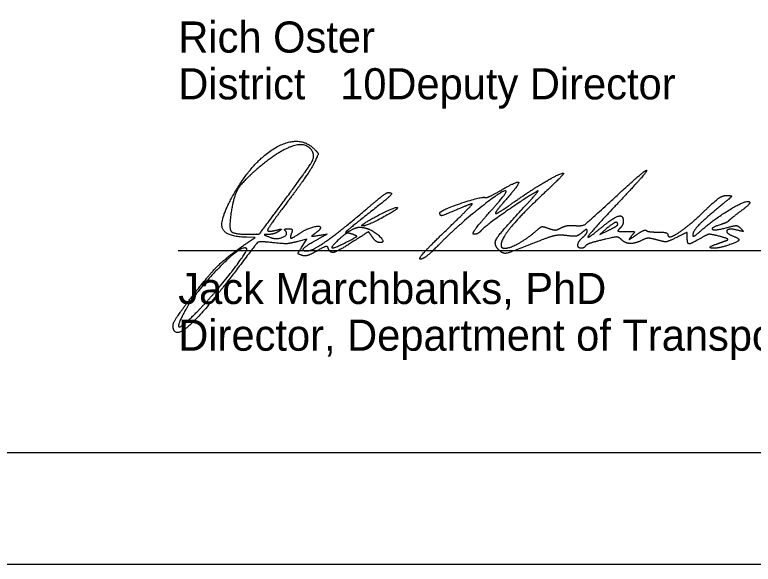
# Model space of a CAD drawing. Extents: x -10 to 158, y 8 to 33.
# Drawn here: x 149.672 to 152.994, y 10.962 to 13.431 of the extents above; entities that cross this region are included whole.
import ezdxf

# ---------------------------------------------------------------- set-up
doc = ezdxf.new("R2010")
doc.units = 0
for name, color, linetype in [('SH_Border', 7, 'Continuous'), ('SH_Cut_Line', 7, 'Continuous'), ('SH_Data', 7, 'Continuous'), ('SH_Text', 7, 'Continuous')]:
    doc.layers.add(name, color=color, linetype=linetype)

msp = doc.modelspace()

# ---------------------------------------------------------------- linework, layer by layer
at = {"layer": 'SH_Border'}
msp.add_lwpolyline([(125.5038, 32.4623), (157.5038, 32.4623), (157.5038, 11.4623), (125.5038, 11.4623)], close=True, dxfattribs=at)
at = {"layer": 'SH_Cut_Line'}
msp.add_lwpolyline([(124.0038, 10.9623), (158.0038, 10.9623), (158.0038, 32.9623), (124.0038, 32.9623)], close=True, dxfattribs=at)
at = {"layer": 'SH_Data'}
msp.add_line((150.4076, 12.3716), (153.9076, 12.3716), dxfattribs=at)
at = {"layer": 'SH_Text'}
for p, q in [((150.8699, 12.5767), (150.8699, 12.5767)), ((152.3842, 12.4888), (152.3842, 12.4888)), ((151.2353, 12.4868), (151.2353, 12.4868)), ((151.6071, 12.4578), (151.6071, 12.4578)), ((151.1905, 12.4452), (151.1905, 12.4452))]:
    msp.add_line(p, q, dxfattribs=at)
for points in [[(152.3325, 12.4691), (152.303, 12.4435), (152.3436, 12.4632)], [(150.7223, 12.4097), (150.753, 12.431), (150.7151, 12.4316)], [(150.9652, 12.3899), (150.9864, 12.4222), (150.9447, 12.4121)]]:
    msp.add_lwpolyline(points, dxfattribs=at)
for points in [[(150.6586, 12.6274), (150.7449, 12.7778), (150.953, 12.8939), (151.0187, 12.8282)], [(151.0097, 12.819), (150.9837, 12.861), (150.8576, 12.8199), (150.7623, 12.7382)], [(151.0187, 12.8282), (151.0374, 12.8094), (151.0375, 12.8044), (151.0191, 12.7659)], [(150.8699, 12.5767), (150.9913, 12.7401), (151.0237, 12.7963), (151.0097, 12.819)], [(151.0191, 12.7659), (151.0082, 12.743), (150.9565, 12.6674), (150.9042, 12.598)], [(150.7623, 12.7382), (150.6956, 12.6812), (150.6568, 12.6171), (150.6457, 12.5458)], [(152.3666, 12.6063), (152.4416, 12.6754), (152.5077, 12.732), (152.5134, 12.7321)], [(152.5134, 12.7321), (152.5191, 12.7322), (152.4671, 12.672), (152.3978, 12.5984)], [(151.9123, 12.5859), (151.9929, 12.6425), (152.1242, 12.7198), (152.1399, 12.7198)], [(152.1399, 12.7198), (152.1448, 12.7198), (152.1035, 12.6771), (152.0481, 12.6251)], [(151.8534, 12.6394), (151.9321, 12.6856), (151.9444, 12.6723), (151.8851, 12.605)], [(150.7151, 12.4316), (150.6172, 12.4333), (150.5938, 12.5144), (150.6586, 12.6274)], [(151.2487, 12.5539), (151.2992, 12.5968), (151.3447, 12.632), (151.3498, 12.6321)], [(151.3498, 12.6321), (151.3747, 12.6326), (151.3513, 12.607), (151.2655, 12.5398)], [(151.8815, 12.6392), (151.8718, 12.6488), (151.6621, 12.4819), (151.5842, 12.4026)], [(152.0217, 12.6387), (151.9727, 12.6109), (151.7843, 12.4787), (151.7711, 12.4628)], [(151.7877, 12.6102), (151.7933, 12.6084), (151.8228, 12.6215), (151.8534, 12.6394)], [(151.8036, 12.5388), (151.8499, 12.5905), (151.885, 12.6357), (151.8815, 12.6392)], [(152.0481, 12.6251), (151.9485, 12.5313), (151.8592, 12.4232), (151.8592, 12.3962)], [(151.9565, 12.5598), (152.0027, 12.609), (152.032, 12.6446), (152.0217, 12.6387)], [(150.9042, 12.598), (150.852, 12.5287), (150.8092, 12.468), (150.8092, 12.4632)], [(151.5844, 12.5416), (151.5846, 12.5522), (151.772, 12.6154), (151.7877, 12.6102)], [(151.8851, 12.605), (151.8571, 12.5732), (151.8342, 12.5435), (151.8342, 12.5391)], [(152.1916, 12.4839), (152.2251, 12.4811), (152.2486, 12.4975), (152.3666, 12.6063)], [(152.3978, 12.5984), (152.2682, 12.4609), (152.2361, 12.4136), (152.3183, 12.4814)], [(152.7561, 12.4589), (152.8097, 12.5077), (152.9567, 12.5977), (152.9736, 12.5921)], [(152.7749, 12.5501), (152.82, 12.5939), (152.8572, 12.6196), (152.8749, 12.6192)], [(152.8749, 12.6192), (152.8992, 12.6187), (152.8953, 12.6124), (152.8467, 12.5723)], [(152.9736, 12.5921), (152.9819, 12.5893), (152.9667, 12.5705), (152.9396, 12.5503)], [(150.7238, 12.4448), (150.7705, 12.4448), (150.775, 12.4489), (150.8699, 12.5767)], [(151.2353, 12.4868), (151.2556, 12.5047), (151.3877, 12.5705), (151.3928, 12.5653)], [(151.3928, 12.5653), (151.399, 12.5591), (151.2564, 12.4823), (151.2387, 12.4823)], [(151.6655, 12.5573), (151.6029, 12.5304), (151.5841, 12.5268), (151.5844, 12.5416)], [(151.6071, 12.4578), (151.6781, 12.5262), (151.7334, 12.5823), (151.73, 12.5823)], [(151.73, 12.5823), (151.7266, 12.5823), (151.6975, 12.571), (151.6655, 12.5573)], [(151.8494, 12.3742), (151.8242, 12.3994), (151.8532, 12.4495), (151.9565, 12.5598)], [(151.8342, 12.5391), (151.8342, 12.5346), (151.8694, 12.5557), (151.9123, 12.5859)], [(152.8467, 12.5723), (152.7727, 12.5114), (152.7217, 12.4579), (152.7217, 12.4411)], [(150.6457, 12.5458), (150.6343, 12.4725), (150.6557, 12.4448), (150.7238, 12.4448)], [(150.9874, 12.3698), (151.0105, 12.3698), (151.1365, 12.4586), (151.2487, 12.5539)], [(151.2655, 12.5398), (151.1722, 12.4667), (151.1508, 12.4452), (151.1947, 12.4687)], [(151.7378, 12.4448), (151.7275, 12.4448), (151.7564, 12.486), (151.8036, 12.5388)], [(152.3183, 12.4814), (152.3667, 12.5213), (152.4092, 12.5316), (152.4092, 12.5035)], [(152.6092, 12.4433), (152.6092, 12.4204), (152.7045, 12.4819), (152.7749, 12.5501)], [(152.9396, 12.5503), (152.9126, 12.5302), (152.8877, 12.5102), (152.8842, 12.5059)], [(152.3842, 12.4888), (152.3842, 12.5023), (152.3601, 12.4931), (152.3325, 12.4691)], [(152.3436, 12.4632), (152.3659, 12.474), (152.3842, 12.4856), (152.3842, 12.4888)], [(152.4092, 12.5035), (152.4092, 12.4946), (152.4025, 12.4805), (152.3942, 12.4723)], [(152.8498, 12.4894), (152.8003, 12.4739), (152.8198, 12.4602), (152.8717, 12.4741)], [(152.8842, 12.5059), (152.8808, 12.5016), (152.8653, 12.4942), (152.8498, 12.4894)], [(150.8092, 12.4632), (150.8092, 12.4585), (150.8247, 12.4581), (150.8436, 12.4625)], [(150.8592, 12.4578), (150.8489, 12.4509), (150.8292, 12.4447), (150.8155, 12.4442)], [(150.8196, 12.4315), (150.8495, 12.4195), (150.9057, 12.4441), (150.8883, 12.4615)], [(150.8436, 12.4625), (150.8691, 12.4685), (150.8731, 12.4672), (150.8592, 12.4578)], [(150.8883, 12.4615), (150.8838, 12.466), (150.89, 12.4698), (150.9022, 12.4698)], [(150.9022, 12.4698), (150.9168, 12.4698), (150.9219, 12.4633), (150.9172, 12.451)], [(150.9533, 12.4491), (150.9822, 12.4689), (151.0467, 12.4864), (151.0467, 12.4745)], [(151.0467, 12.4745), (151.0467, 12.47), (151.037, 12.4591), (151.0251, 12.4504)], [(151.1947, 12.4687), (151.2073, 12.4754), (151.2312, 12.4775), (151.2478, 12.4733)], [(151.2809, 12.4319), (151.264, 12.456), (151.262, 12.4556), (151.1962, 12.4132)], [(151.2387, 12.4823), (151.234, 12.4823), (151.2324, 12.4843), (151.2353, 12.4868)], [(151.2478, 12.4733), (151.2839, 12.4642), (151.3423, 12.4073), (151.3156, 12.4073)], [(151.4967, 12.333), (151.4864, 12.3332), (151.5361, 12.3893), (151.6071, 12.4578)], [(151.7711, 12.4628), (151.7629, 12.4529), (151.7479, 12.4448), (151.7378, 12.4448)], [(151.8773, 12.3823), (151.899, 12.3823), (151.9803, 12.4275), (152.0167, 12.4598)], [(152.0167, 12.4598), (152.037, 12.4778), (152.0499, 12.4804), (152.0736, 12.4714)], [(152.0736, 12.4714), (152.0938, 12.4637), (152.1126, 12.4644), (152.1286, 12.4735)], [(152.1286, 12.4735), (152.142, 12.481), (152.1704, 12.4857), (152.1916, 12.4839)], [(152.2467, 12.4607), (152.2467, 12.4678), (152.2366, 12.4644), (152.2241, 12.4532)], [(152.228, 12.4323), (152.2383, 12.4408), (152.2467, 12.4536), (152.2467, 12.4607)], [(152.3942, 12.4723), (152.3825, 12.4606), (152.3884, 12.4573), (152.4207, 12.4573)], [(152.4207, 12.4573), (152.4583, 12.4573), (152.4606, 12.4552), (152.4451, 12.4359)], [(152.4669, 12.4418), (152.4883, 12.4568), (152.509, 12.4658), (152.5129, 12.4619)], [(152.5129, 12.4619), (152.5168, 12.458), (152.5401, 12.4548), (152.5646, 12.4548)], [(152.7217, 12.4411), (152.7217, 12.4337), (152.7372, 12.4417), (152.7561, 12.4589)], [(152.8717, 12.4741), (152.91, 12.4843), (152.9252, 12.4837), (152.9373, 12.4714)], [(152.9186, 12.464), (152.8819, 12.4731), (152.8686, 12.45), (152.903, 12.4368)], [(152.9373, 12.4714), (152.95, 12.4585), (152.9464, 12.4571), (152.9186, 12.464)], [(150.8155, 12.4442), (150.7931, 12.4433), (150.7935, 12.442), (150.8196, 12.4315)], [(150.9172, 12.451), (150.9083, 12.4278), (150.9211, 12.4271), (150.9533, 12.4491)], [(151.0251, 12.4504), (151.0062, 12.4366), (151.0082, 12.4353), (151.0407, 12.4403)], [(151.0407, 12.4403), (151.0775, 12.4458), (151.0774, 12.4456), (151.0319, 12.4204)], [(151.1373, 12.4286), (151.0931, 12.3882), (151.1043, 12.3793), (151.1623, 12.4089)], [(151.1905, 12.4452), (151.1732, 12.4515), (151.1567, 12.4464), (151.1373, 12.4286)], [(151.1623, 12.4089), (151.2087, 12.4325), (151.2123, 12.4371), (151.1905, 12.4452)], [(151.3156, 12.4073), (151.306, 12.4073), (151.2904, 12.4184), (151.2809, 12.4319)], [(152.1546, 12.4388), (152.1254, 12.4425), (152.0856, 12.4361), (152.0491, 12.4217)], [(152.2241, 12.4532), (152.2085, 12.439), (152.1872, 12.4346), (152.1546, 12.4388)], [(152.221, 12.3823), (152.2026, 12.3823), (152.2072, 12.415), (152.228, 12.4323)], [(152.3996, 12.4219), (152.3885, 12.433), (152.3685, 12.4325), (152.3153, 12.4197)], [(152.4451, 12.4359), (152.4331, 12.4209), (152.4396, 12.4226), (152.4669, 12.4418)], [(152.5604, 12.4194), (152.5335, 12.4271), (152.5104, 12.4271), (152.4959, 12.4193)], [(152.6495, 12.4308), (152.6121, 12.4123), (152.5936, 12.4099), (152.5604, 12.4194)], [(152.5646, 12.4548), (152.5892, 12.4548), (152.6092, 12.4496), (152.6092, 12.4433)], [(152.6967, 12.4307), (152.6967, 12.4536), (152.6956, 12.4536), (152.6495, 12.4308)], [(152.7587, 12.4277), (152.7136, 12.4011), (152.6967, 12.4019), (152.6967, 12.4307)], [(152.8418, 12.4357), (152.803, 12.4456), (152.7862, 12.444), (152.7587, 12.4277)], [(152.8717, 12.4165), (152.8831, 12.4206), (152.8714, 12.4282), (152.8418, 12.4357)], [(152.903, 12.4368), (152.9335, 12.4251), (152.9246, 12.4102), (152.8779, 12.3947)], [(150.4713, 12.1675), (150.549, 12.268), (150.6291, 12.3453), (150.7223, 12.4097)], [(150.8035, 12.4098), (150.7701, 12.4132), (150.7583, 12.4027), (150.6817, 12.301)], [(150.9447, 12.4121), (150.9043, 12.4024), (150.882, 12.402), (150.8035, 12.4098)], [(150.964, 12.3498), (150.9458, 12.3568), (150.9459, 12.3605), (150.9652, 12.3899)], [(151.0319, 12.4204), (150.9808, 12.3922), (150.9611, 12.3698), (150.9874, 12.3698)], [(151.0817, 12.3835), (151.0789, 12.392), (151.0597, 12.3868), (151.0306, 12.3697)], [(151.1962, 12.4132), (151.1273, 12.3688), (151.0899, 12.3591), (151.0817, 12.3835)], [(151.5842, 12.4026), (151.5464, 12.3641), (151.507, 12.3328), (151.4967, 12.333)], [(152.0491, 12.4217), (151.903, 12.364), (151.868, 12.3556), (151.8494, 12.3742)], [(151.8592, 12.3962), (151.8592, 12.3885), (151.8673, 12.3823), (151.8773, 12.3823)], [(152.2391, 12.3926), (152.2356, 12.3869), (152.2274, 12.3823), (152.221, 12.3823)], [(152.3153, 12.4197), (152.2769, 12.4105), (152.2427, 12.3983), (152.2391, 12.3926)], [(152.4959, 12.4193), (152.4652, 12.4029), (152.4173, 12.4041), (152.3996, 12.4219)], [(152.8779, 12.3947), (152.8313, 12.3793), (152.7839, 12.3851), (152.828, 12.4008)], [(152.828, 12.4008), (152.8417, 12.4057), (152.8614, 12.4127), (152.8717, 12.4165)], [(150.7151, 12.3805), (150.6942, 12.4014), (150.4757, 12.1757), (150.4294, 12.0854)], [(150.4995, 12.1041), (150.5671, 12.1732), (150.7228, 12.3728), (150.7151, 12.3805)], [(151.0306, 12.3697), (151.005, 12.3545), (150.975, 12.3456), (150.964, 12.3498)], [(150.6817, 12.301), (150.5293, 12.0989), (150.3842, 11.9703), (150.3842, 12.0373)], [(150.3842, 12.0373), (150.3842, 12.0469), (150.4234, 12.1055), (150.4713, 12.1675)], [(150.4294, 12.0854), (150.3981, 12.0244), (150.4298, 12.0329), (150.4995, 12.1041)]]:
    msp.add_open_spline(points, degree=2, dxfattribs=at)

# ---------------------------------------------------------------- texts
for s, p in [('Rich Oster', (150.4076, 13.2611)), ('District       Deputy Director', (150.4076, 13.0511)), ('              10', (150.4076, 13.0511)), ('Jack Marchbanks, PhD', (150.4076, 12.1316)), ('Director, Department of Transportation', (150.4076, 11.9216))]:
    msp.add_text(s, height=0.14, dxfattribs=at).set_placement(p)

doc.saveas('drawing.dxf')
